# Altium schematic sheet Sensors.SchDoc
size A; DocumentNumber: 4; SheetNumber: 4; SheetTotal: 5
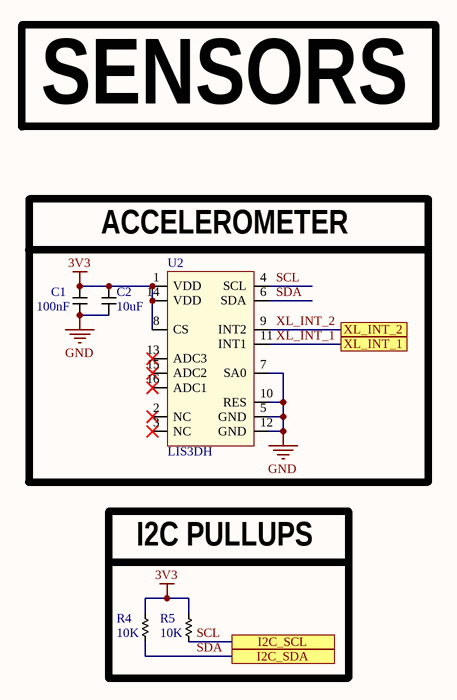
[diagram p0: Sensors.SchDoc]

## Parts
C1  100nF  [CAP_0603_HIGH]
C2  10uF  [CAP_0603_HIGH]
R4  10K  [RES_0603_HIGH]
R5  10K  [RES_0603_HIGH]
U2  LIS3DH  [LIS3DH]

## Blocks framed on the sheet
ACCELEROMETER: C1 C2 U2
I2C PULLUPS: R4 R5

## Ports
I2C_SCL, I2C_SDA, XL_INT_1, XL_INT_2

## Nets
3V3: C1.1 C2.1 R4.2 R5.2 U2.1(VDD) U2.8(CS) U2.14(VDD)
GND: C1.2 C2.2 U2.5(GND) U2.7(SA0) U2.10(RES) U2.12(GND)
SCL: R5.1 U2.4(SCL) ; port I2C_SCL
SDA: R4.1 U2.6(SDA) ; port I2C_SDA
XL_INT_1: U2.11(INT1) ; port XL_INT_1
XL_INT_2: U2.9(INT2) ; port XL_INT_2

Not connected (* = marked no-connect by the designer): U2 2(NC)* 3(NC)* 13(ADC3)* 15(ADC2)* 16(ADC1)*

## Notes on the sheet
- SENSORS

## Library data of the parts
C1 C2 = Capacitor_0603: 0603 Capacitor
R4 R5 = Resistor_0603: 0603 Resistor
U2 = LIS3DH: LIS3DH ACCEL 2-16G I2C/SPI 16LGA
